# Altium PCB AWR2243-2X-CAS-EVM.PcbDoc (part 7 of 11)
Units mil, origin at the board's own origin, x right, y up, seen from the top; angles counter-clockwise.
Board outline 5118.11 x 3937.01 mil, 8 copper layers (Layer 1 - Top Layer, Layer 2 - GND, Layer 3 - Signal (Sensitive), Layer 4 - GND / Signal, Layer 5 - Signal, Layer 6 - PWR / Signal, Layer 7 - GND, Layer 8 - Bottom Layer), stack 54.8 mil thick; 629 components, 407 nets, 2243 pads, 3950 vias.
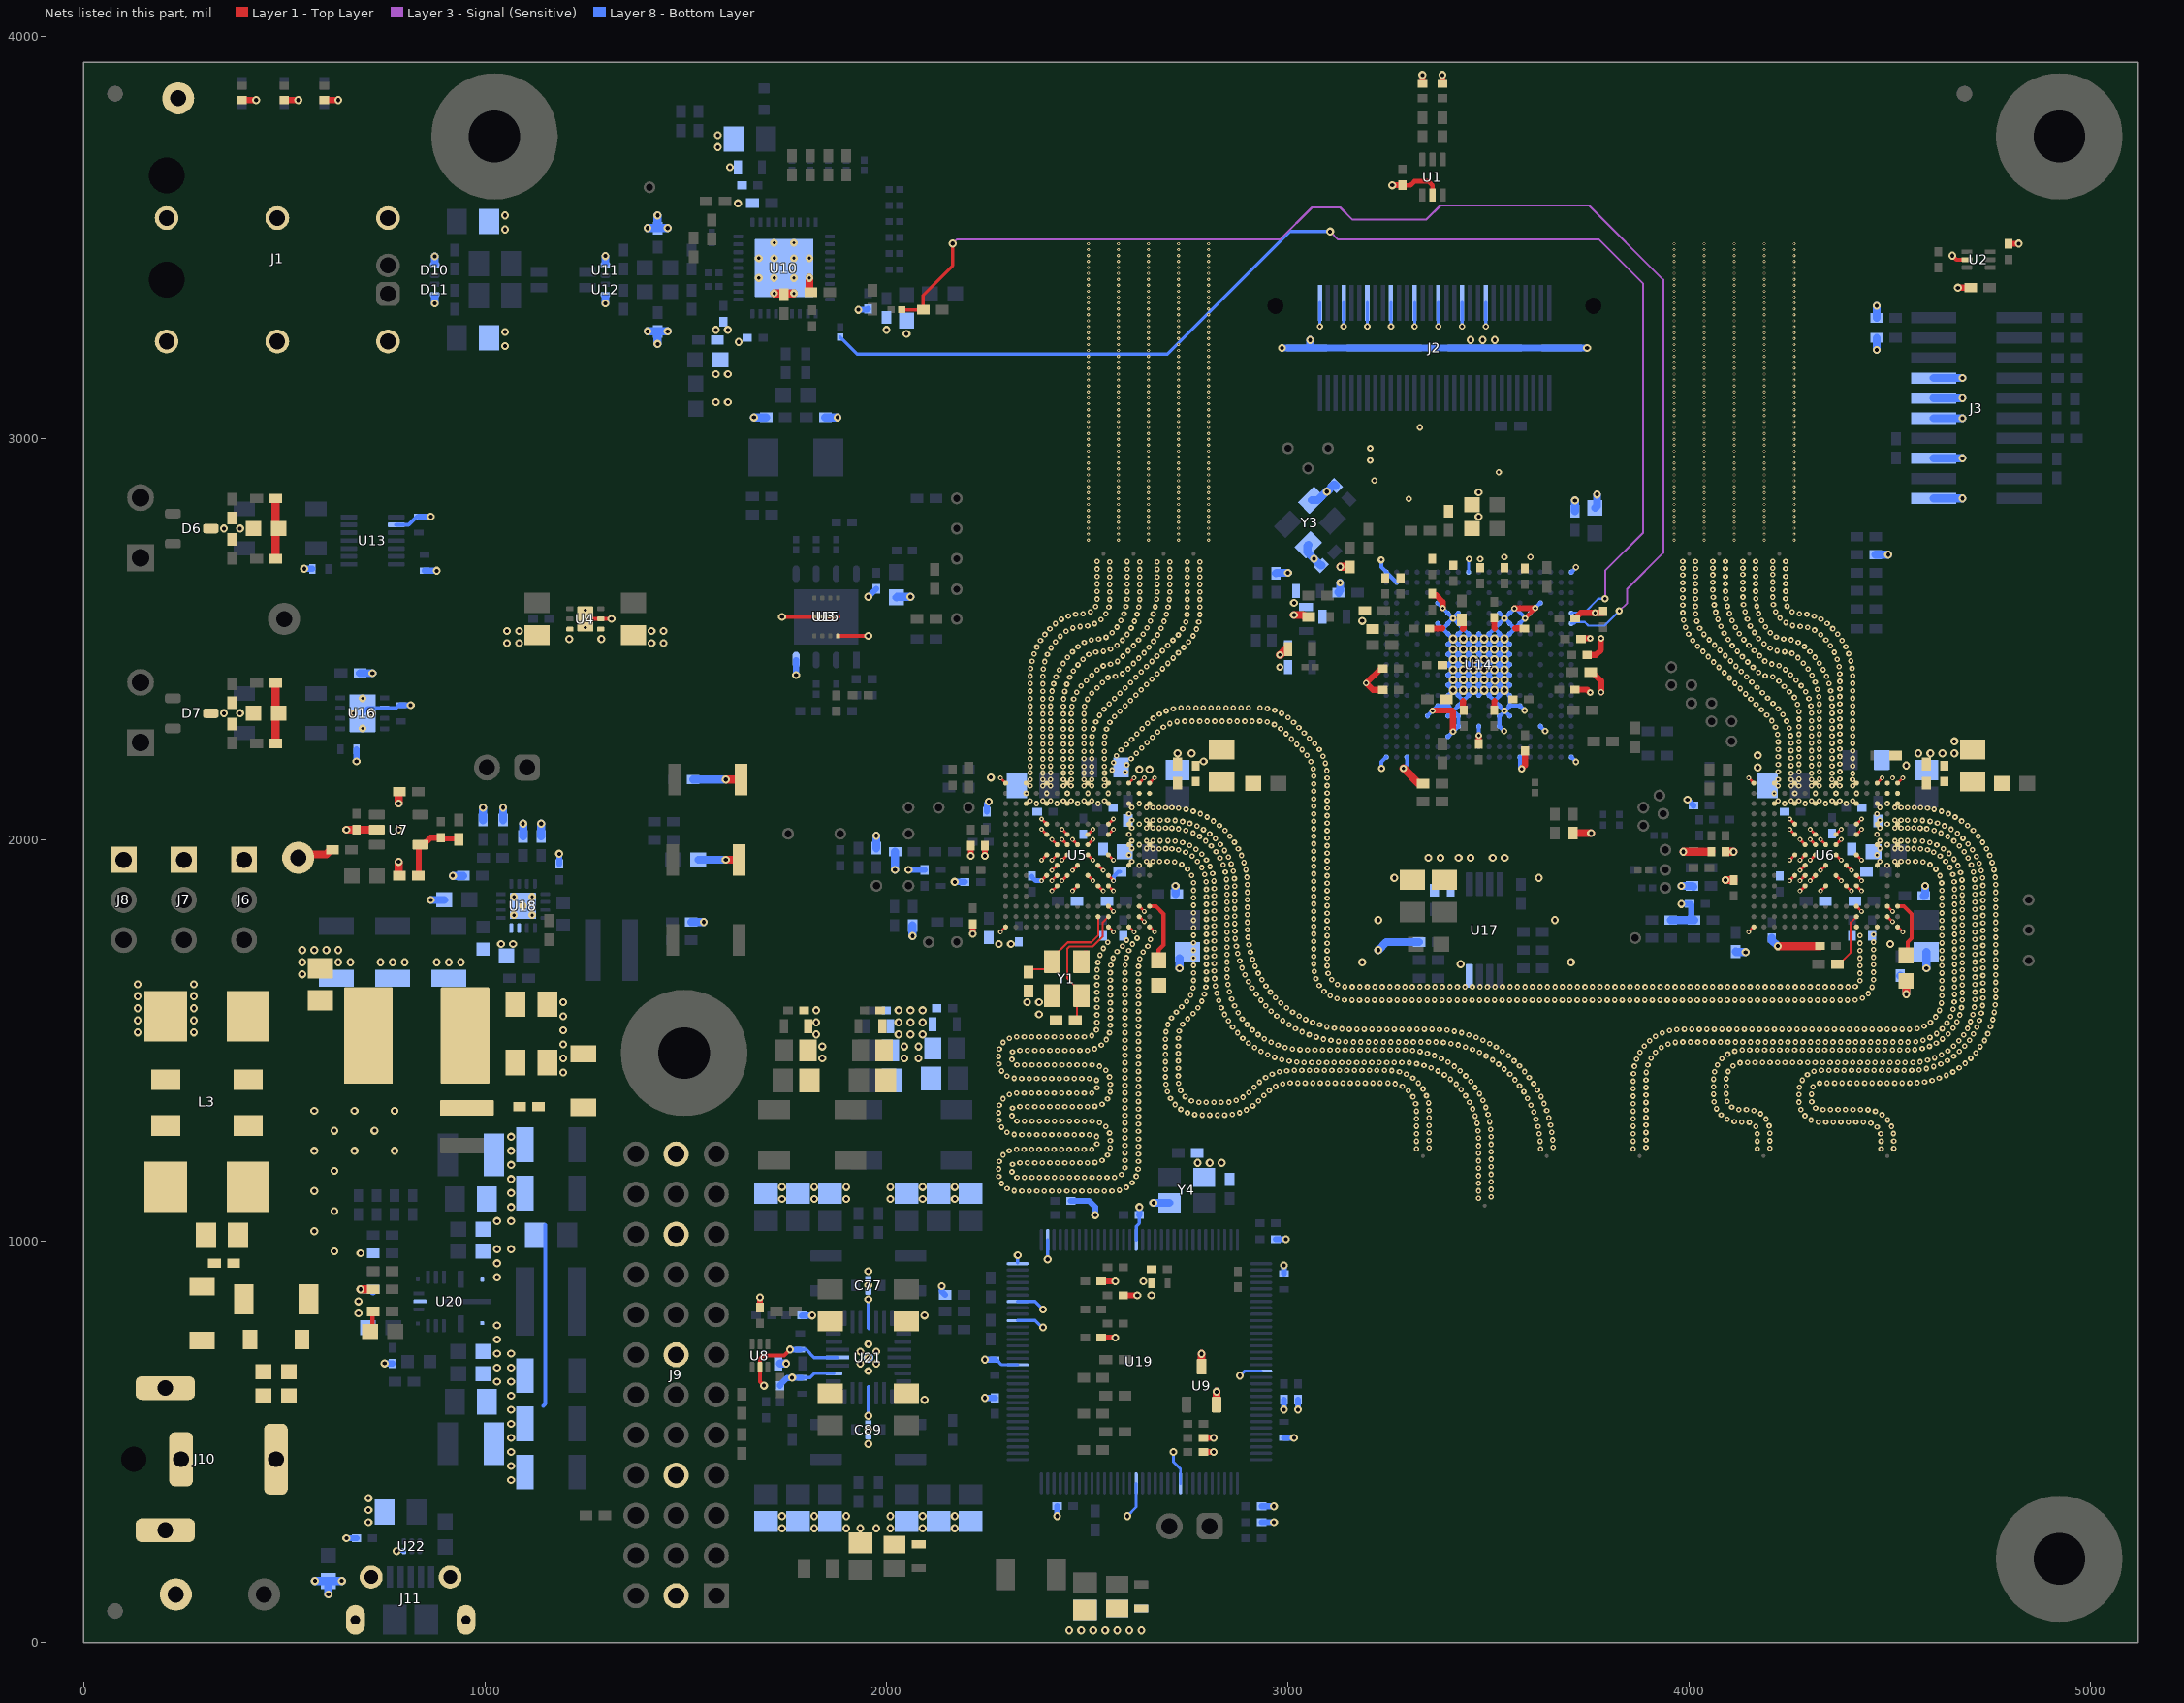
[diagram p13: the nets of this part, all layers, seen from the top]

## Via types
v1: diameter 13.78, hole 5.91, Layer 1 - Top Layer to Layer 2 - GND, tented top, 2104 vias
v2: diameter 20, hole 10, Layer 1 - Top Layer to Layer 8 - Bottom Layer, tented both sides, 831 vias
v3: diameter 7.87, hole 3.94, Layer 1 - Top Layer to Layer 2 - GND, tented top, 510 vias
v4: diameter 12, hole 6, Layer 1 - Top Layer to Layer 8 - Bottom Layer, tented both sides, 176 vias
v5: diameter 16, hole 8, Layer 1 - Top Layer to Layer 8 - Bottom Layer, tented both sides, 138 vias
v6: diameter 13.78, hole 5.91, Layer 1 - Top Layer to Layer 2 - GND, tented both sides, 88 vias
v7: diameter 18, hole 8, Layer 1 - Top Layer to Layer 8 - Bottom Layer, tented both sides, 41 vias
v8: diameter 22, hole 12, Layer 1 - Top Layer to Layer 8 - Bottom Layer, tented both sides, 36 vias
v9: diameter 19.68, hole 7.87, Layer 1 - Top Layer to Layer 8 - Bottom Layer, tented both sides, 26 vias

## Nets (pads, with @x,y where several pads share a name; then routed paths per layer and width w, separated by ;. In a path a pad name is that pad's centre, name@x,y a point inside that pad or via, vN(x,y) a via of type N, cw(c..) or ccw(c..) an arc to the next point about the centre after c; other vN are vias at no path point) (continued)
GND: (continued)
  other v1: 3474.49,1106.77 3506.14,1110.42 2337.18,1125.32 2355.88,1125.32 2374.58,1125.32 2393.28,1125.32 2411.98,1125.32 2430.68,1125.32 2449.38,1125.32 2468.08,1125.32 2486.78,1125.32 2505.48,1125.32 2524.18,1125.32 2542.89,1125.32 2561.59,1125.32 3474.49,1125.47 2318.48,1125.7 2580.21,1127 3506.14,1129.12 2300.56,1131.04 2597.58,1133.93 2286.82,1143.73 3474.49,1144.17 2611.96,1145.89 3506.14,1147.82 2325.03,1158.7 2343.73,1158.7 2362.43,1158.7 2381.14,1158.7 2399.84,1158.7 2418.54,1158.7 2437.24,1158.7 2455.94,1158.7 2474.64,1158.7 2493.34,1158.7 2512.04,1158.7 2530.74,1158.7 2549.44,1158.7 2568.14,1158.76 2280.12,1161.18 2622,1161.67 3474.49,1162.87 2585.37,1166.03 3506.14,1166.52 2312.68,1172.74 2279.29,1179.87 2626.9,1179.71 3474.49,1181.57 2593.94,1182.65 3506.14,1185.22 2314.02,1191.39 2332.31,1195.32 2351.01,1195.32 2369.71,1195.32 2388.41,1195.32 2407.11,1195.32 2425.81,1195.32 2444.51,1195.32 2463.21,1195.32 2481.91,1195.32 2500.61,1195.32 2519.31,1195.81 2281.2,1198.47 2627.68,1198.4 3474.49,1200.27 2537.14,1201.44 2594.29,1201.35 3506.14,1203.92 2550.65,1214.37 2290.29,1214.81 2627.68,1217.1 3474.49,1218.97 2594.29,1220.05 3506.14,1222.62 2305.73,1225.37 2324.13,1228.7 2342.83,1228.7 2361.53,1228.7 2380.23,1228.7 2398.93,1228.7 2417.63,1228.7 2436.33,1228.7 2455.03,1228.7 2473.73,1228.7 2492.43,1228.7 2511.14,1228.7 3320.2,1230.2 3628.93,1230.19 3860.16,1230.2 4168.7,1230.2 4477.25,1230.2 4200.35,1231.32 4508.9,1230.74 2556.96,1231.98 3351.85,1232.21 3891.81,1233.36 3660.27,1233.62 2627.68,1235.8 3474.49,1237.68 2594.29,1238.75 3506.14,1241.33 2524.29,1241.99 3320.2,1248.9 3627.91,1248.86 3860.16,1248.9 4168.7,1248.9 4477.25,1248.9 4508.9,1249.44 4200.35,1250.02 2557.68,1250.67 3351.85,1250.91 3659.22,1252.29 3891.81,1252.06 2627.68,1254.5 3474.49,1256.38 2594.29,1257.45 3506.13,1260.03 2523.42,1260.67 2337,1265.32 2355.7,1265.32 2374.4,1265.32 2393.11,1265.32 2411.81,1265.32 2430.51,1265.32 2449.21,1265.32 2467.91,1265.32 2486.61,1265.32 2505.31,1265.32 2318.31,1265.72 3625.92,1267.45 3320.2,1267.6 3860.16,1267.6 4168.7,1267.6 4476.28,1267.57 4507.93,1268.12 2555.59,1269.25 4200.35,1268.72 3351.85,1269.61 2300.41,1271.14 3657.25,1270.89 3891.81,1270.76 2627.68,1273.2 3473.61,1275.06 2594.29,1276.15 3504.9,1278.69 2286.71,1283.87 4467.47,1284.07 2546.17,1285.41 3320.2,1286.3 3622.79,1285.89 3860.16,1286.3 4164.88,1285.9 4502.93,1286.14 4198.4,1287.32 3351.85,1288.31 3654.11,1289.32 3891.81,1289.46 2627.68,1291.9 3470.91,1293.56 4451.76,1294.22 2594.29,1294.85 2530.54,1295.66 4130.33,1296.18 4149.03,1295.82 4339.66,1296.18 4358.36,1296.18 4377.06,1296.18 4395.76,1296.18 4414.46,1296.18 4433.17,1296.18 3502.26,1297.2 4320.97,1296.73 4111.68,1297.58 2325.08,1298.7 2343.78,1298.7 2362.48,1298.7 2381.18,1298.7 2399.88,1298.7 2418.58,1298.7 2437.28,1298.7 2455.98,1298.7 2474.68,1298.7 2493.38,1298.7 2512.08,1298.7 2280.09,1301.36 4302.94,1301.7 4493.26,1302.14 3617.92,1303.95 4094,1303.65 4190.46,1304.25 3320.2,1305 3860.16,1305 3351.85,1307.01 3649.64,1307.48 3891.81,1308.16 2627.68,1310.6 3466.54,1311.75 2312.68,1312.7 4287.69,1312.53 2594.29,1313.55 2786.54,1314.17 2805.24,1314.17 2823.94,1314.17 2842.64,1314.17 2767.87,1315.31 4078.96,1314.77 4479.63,1314.94 2861.28,1315.65 3498.49,1315.52 4177.3,1317.53 2279.29,1320.04 2749.74,1319.9 2879.46,1320.03 3612.25,1321.77 3320.2,1323.7 3860.16,1323.7 4463.05,1323.59 3644.46,1325.45 3351.85,1325.71 4160.48,1325.72 2896.74,1327.18 3891.81,1326.86 4444.75,1327.46 2733.12,1328.46 4123.2,1327.79 4141.9,1327.83 4277.44,1328.17 4332.55,1327.83 4351.25,1327.83 4369.95,1327.83 4388.65,1327.83 4407.35,1327.83 4426.05,1327.83 2627.68,1329.3 3460.53,1329.45 4067.75,1329.74 2314,1331.35 4314.19,1331.42 2594.29,1332.25 3492.48,1333.22 4105.48,1333.75 2332.28,1335.32 2350.98,1335.32 2369.68,1335.32 2388.38,1335.32 2407.08,1335.32 2425.78,1335.32 2444.48,1335.32 2463.18,1335.32 2481.88,1335.32 2500.58,1335.32 2519.28,1335.81 2912.6,1337.09 2281.23,1338.64 3605.09,1339.04 2718.76,1340.45 2537.11,1341.43 3318.2,1342.29 3860.16,1342.4 3637.57,1342.83 3350.2,1344.34 2777.91,1345.93 2796.61,1345.83 2815.31,1345.83 2834.02,1345.83 2852.71,1346.47 3452.28,1346.24 3891.81,1345.56 4272.92,1346.32 4061.59,1347.4 4304.5,1347.41 2627.68,1348 2926.73,1349.35 4094.01,1348.53 2759.61,1349.78 2870.97,1350.51 3485.27,1350.48 2594.29,1350.95 2550.63,1354.35 2290.39,1354.95 2707.51,1355.39 3596.7,1355.76 2887.91,1358.42 2743.95,1359.99 3311.2,1359.64 3630.28,1360.05 3860.16,1361.1 3345,1362.31 3442.55,1362.2 2939.95,1362.57 3891.81,1364.26 2305.88,1365.43 4272.6,1365.01 4060.16,1366.04 4304.25,1366.11 2627.68,1366.7 3476.88,1367.2 4091.81,1367.1 2324.29,1368.7 2342.99,1368.7 2361.69,1368.7 2380.39,1368.7 2399.09,1368.7 2417.8,1368.7 2436.5,1368.7 2455.2,1368.7 2473.9,1368.7 2492.6,1368.7 2511.3,1368.7 2594.29,1369.65 2902.69,1369.87 2556.95,1371.95 2699.77,1372.41 3587.58,1372.08 2732.73,1374.95 2953.64,1375.31 3299.97,1374.59 3621.23,1376.42 3431.41,1377.23 3336.54,1378.98 3860.16,1379.8 2524.29,1382.15 2915.82,1383.2 3466.61,1382.82 3891.81,1382.96 4273.93,1383.67 4307.93,1384.45 2627.68,1385.41 2969.43,1385.33 3284.78,1385.49 4060.16,1384.74 4091.81,1385.8 3576.76,1387.33 2594.29,1388.36 2557.68,1390.64 2695.91,1390.71 3418.96,1391.18 2987.02,1391.67 3267.33,1392.23 3611.67,1392.49 2727.31,1392.85 3005.59,1393.92 3024.29,1393.82 3042.99,1393.82 3061.69,1393.82 3080.39,1393.82 3099.09,1393.82 3117.79,1393.82 3136.49,1393.82 3155.19,1393.82 3173.89,1393.82 3192.6,1393.82 3211.3,1393.82 3230,1393.82 3248.7,1393.82 3325.1,1393.77 4324.18,1393.7 4342.88,1393.82 4361.59,1393.82 4380.29,1393.82 4398.99,1393.82 4417.69,1393.82 4436.39,1393.82 4455.09,1393.82 4473.79,1393.82 4492.49,1393.82 4511.19,1393.82 4529.89,1393.82 4548.59,1393.82 4567.27,1394.73 2929.41,1396.04 4585.86,1396.83 3455.29,1397.71 3860.16,1398.5 4604.2,1400.48 2523.32,1400.82 4280.98,1400.99 3565.19,1402.03 3891.81,1401.66 4060.2,1403.44 2627.68,1404.11 3404.9,1403.51 4091.77,1404.5 2336.86,1405.32 2355.56,1405.32 2374.26,1405.32 2392.96,1405.32 2411.66,1405.32 2430.36,1405.32 2449.07,1405.32 2467.77,1405.32 2486.47,1405.32 2505.17,1405.32 2318.16,1405.74 3311.08,1406.16 4621.99,1406.22 2594.29,1407.06 2944.36,1407.27 3600.85,1407.74 2555.61,1409.22 2695.16,1409.39 2300.28,1411.22 2726.81,1411.55 3442.96,1411.77 4639.35,1413.17 3389.7,1414.4 4293.81,1414.59 2960.93,1415.94 3295,1415.7 3552.73,1415.97 3860.61,1417.2 3892.44,1420.36 4656.13,1421.45 2978.68,1421.83 3277.41,1422.04 3589.2,1422.37 4062.89,1421.95 2627.68,1422.81 4096.54,1422.58 4310.4,1423.23 2286.62,1423.98 3373.57,1423.86 3429.01,1424.22 2546.2,1425.38 2997.15,1424.78 3015.84,1425.47 3034.54,1425.47 3053.24,1425.47 3071.94,1425.47 3090.64,1425.47 3109.34,1425.47 3128.04,1425.47 3146.74,1425.47 3165.44,1425.47 3184.14,1425.47 3202.84,1425.47 3221.54,1425.47 3240.24,1425.47 3258.94,1424.98 4328.96,1425.47 4347.66,1425.47 4366.37,1425.47 4385.07,1425.47 4403.77,1425.47 4422.47,1425.47 4441.17,1425.47 4459.87,1425.47 4478.57,1425.47 4497.27,1425.47 4515.97,1425.47 4534.67,1425.47 4553.37,1425.35 2594.29,1425.76 4572.03,1426.57 2695.16,1428.09 3539.01,1428.68 2726.81,1430.25 4590.45,1429.82 3356.65,1431.82 4671.76,1431.7 4608.46,1434.85 2530.57,1435.65 3414.31,1435.78 3576.74,1436.32 3863.06,1435.74 4108.81,1436.69 3338.94,1437.84 2325.11,1438.7 2343.81,1438.7 2362.51,1438.7 2381.21,1438.7 2399.91,1438.7 2418.61,1438.7 2437.31,1438.7 2456.01,1438.7 2474.71,1438.7 2493.42,1438.7 2512.12,1438.7 3896.43,1438.63 4069.97,1439.26 2280.07,1441.5 3524.74,1440.76 2627.68,1441.51 3320.68,1441.89 4625.9,1441.61 4686.65,1443.02 2594.29,1444.46 3302.14,1444.28 4125.94,1444.2 3040.34,1444.91 3059.04,1445 3077.74,1445 3096.44,1445 3115.14,1445 3133.84,1445 3152.54,1445 3171.24,1445 3189.94,1445 3208.65,1445 3227.35,1445 3246.05,1445 3264.75,1445 3283.45,1445 4144.62,1445 4163.32,1445 4182.02,1445 4200.73,1445 4219.43,1445 4238.13,1445 4256.83,1445 4275.53,1445 4294.23,1445 4312.93,1445 4331.63,1445 4350.33,1445 4369.03,1445 4387.73,1445 4406.43,1445 4425.14,1445 4443.84,1445 4462.54,1445 4481.24,1445 4499.94,1445 4518.64,1445 4537.34,1445 4556.04,1445.19 3021.67,1446.1 3398.76,1446.17 2695.16,1446.79 4574.68,1446.66 3003.12,1448.39 2726.81,1448.95 3563.22,1449.24 4642.59,1450.05 4592.94,1450.71 2984.77,1452.04 3509.48,1451.58 2312.68,1452.67 3868.46,1453.64 4081.01,1454.35 3382.13,1454.71 4700.65,1455.42 3904.28,1455.6 4610.68,1456.64 2966.97,1457.75 2279.29,1460.19 2627.68,1460.21 4658.14,1460.44 3493.5,1461.28 3364.99,1462.21 3549.27,1461.7 2594.29,1463.16 2949.51,1464.46 4627.7,1464.37 2695.16,1465.5 4095.74,1465.87 2726.81,1467.65 3347.29,1468.22 4713.07,1469.4 3477.09,1470.26 3876.65,1470.45 3915.62,1470.47 2313.98,1471.32 3329.04,1472.31 4672.48,1472.43 2932.74,1472.73 3534.13,1472.67 4112.89,1473.32 4643.65,1474.14 2332.25,1475.32 2350.95,1475.32 2369.65,1475.32 2388.35,1475.32 2407.05,1475.32 2425.76,1475.32 2444.46,1475.32 2463.16,1475.32 2481.86,1475.32 2500.56,1475.47 3310.57,1475.26 3291.91,1476.48 4131.33,1476.44 3030.1,1477.07 3048.8,1476.65 3067.5,1476.65 3086.2,1476.65 3104.9,1476.65 3123.6,1476.65 3142.3,1476.65 3161,1476.65 3179.7,1476.65 3198.41,1476.65 3217.11,1476.65 3235.81,1476.65 3254.51,1476.65 3273.21,1476.65 3459.81,1477.42 4150.03,1476.65 4168.73,1476.65 4187.44,1476.65 4206.14,1476.65 4224.84,1476.65 4243.54,1476.65 4262.24,1476.65 4280.94,1476.65 4299.64,1476.65 4318.34,1476.65 4337.04,1476.65 4355.74,1476.65 4374.44,1476.65 4393.14,1476.65 4411.84,1476.65 4430.55,1476.65 4449.25,1476.65 4467.95,1476.65 4486.65,1476.65 4505.35,1476.65 4524.05,1476.65 4542.75,1476.65 4561.44,1477.18 2281.26,1478.78 2518.87,1479.27 2627.68,1478.91 3011.48,1478.8 4579.94,1479.95 2594.29,1481.86 2993.14,1482.45 3930,1482.43 2916.84,1482.58 3518.73,1483.28 2695.16,1484.2 3442.21,1483.72 4724.43,1484.25 4597.84,1485.37 2726.81,1486.35 3887.44,1485.73 4658.11,1486.01 4685.59,1485.77 2535.15,1488.46 2975.33,1488.13 3424.24,1488.9 3946.74,1490.77 3405.86,1492.37 3502.36,1492.33 2901.53,1493.32 4614.76,1493.33 2290.48,1495.06 2958.06,1495.32 3387.35,1495.01 3964.88,1495.28 3162.97,1496.18 3181.67,1496.18 3200.37,1496.18 3219.07,1496.18 3237.77,1496.18 3256.47,1496.18 3275.17,1496.18 3293.87,1496.18 3312.57,1496.18 3331.28,1496.18 3349.98,1496.18 3368.68,1496.06 3983.56,1496.18 4002.26,1496.18 4020.97,1496.18 4039.67,1496.18 4058.37,1496.18 4077.07,1496.18 4095.77,1496.18 4114.47,1496.18 4133.17,1496.18 4151.87,1496.18 4170.57,1496.18 4189.27,1496.18 4207.97,1496.18 4226.67,1496.18 4245.37,1496.18 4264.08,1496.18 4282.78,1496.18 4301.48,1496.18 4320.18,1496.18 4338.88,1496.18 4357.58,1496.18 4376.28,1496.18 4394.98,1496.18 4413.68,1496.18 4432.38,1496.18 4451.08,1496.18 4469.78,1496.18 4488.49,1496.18 4507.19,1496.18 4525.89,1496.18 4544.59,1496.18 3144.27,1496.54 4563.26,1497.14 2627.68,1497.61 3125.6,1497.59 3900.54,1499.08 4671.25,1499.3 3107.08,1500.16 4697.33,1500.32 4734.74,1499.86 2594.29,1500.56 3485.67,1500.76 4581.62,1500.73 2547.86,1502.18 2695.16,1502.9 3088.66,1503.38 2941.47,1503.96 4630.34,1503.67 2306,1505.48 2726.81,1505.05 2887.47,1505.65 4599.1,1507.37 3468.39,1507.91 2324.42,1508.7 2343.12,1508.7 2361.82,1508.7 2380.53,1508.7 2399.23,1508.7 2417.93,1508.7 2436.63,1508.7 2455.33,1508.7 2474.03,1508.7 2492.73,1508.7 3070.67,1508.52 3915.6,1510.15 2511.16,1511.86 2925.92,1514.35 3052.9,1514.32 3450.71,1514.01 4682.95,1513.89 2627.68,1516.31 4644.27,1516.15 4707.6,1515.96 4615.21,1516.87 4743.01,1516.63 2555.52,1519.24 2594.29,1519.26 2874.43,1519.05 3432.74,1519.18 3932.25,1518.67 3035.62,1521.48 2696.36,1521.56 3414.4,1522.83 2729.12,1523.61 3950.05,1524.4 2523,1526.34 2911.58,1526.35 3395.96,1525.96 3377.3,1527.09 3968.54,1527.21 3152.9,1527.83 3171.6,1527.83 3190.3,1527.83 3209,1527.83 3227.7,1527.83 3246.41,1527.83 3265.11,1527.83 3283.81,1527.83 3302.51,1527.83 3321.21,1527.83 3339.91,1527.83 3358.61,1527.83 3987.23,1527.83 4005.93,1527.83 4024.64,1527.83 4043.34,1527.83 4062.04,1527.83 4080.74,1527.83 4099.44,1527.83 4118.14,1527.83 4136.84,1527.83 4155.54,1527.83 4174.24,1527.83 4192.94,1527.83 4211.64,1527.83 4230.34,1527.83 4249.04,1527.83 4267.75,1527.83 4286.45,1527.83 4305.15,1527.83 4323.85,1527.83 4342.55,1527.83 4361.25,1527.83 4379.95,1527.83 4398.65,1527.83 4417.35,1527.83 4436.05,1527.83 4454.75,1527.83 4473.45,1527.83 4492.16,1527.83 4510.86,1527.83 4529.56,1527.83 4548.26,1527.83 3134.22,1528.61 4566.91,1529.14 4629.48,1528.95 3018.87,1529.79 4692.72,1529.84 3115.62,1530.62 4656.24,1530.52 2862.17,1533.17 4715.87,1532.73 3097.19,1533.75 4750.02,1533.97 2627.68,1535.01 4584.58,1535.28 2557.68,1537.82 2594.29,1537.96 3002.5,1538.83 3079.18,1538.8 2701.12,1539.65 2737.53,1540.31 2898.31,1539.53 4641.34,1543.41 2524.29,1544.99 3061.48,1544.82 4600.33,1545.36 4666.01,1546.46 4700.26,1546.95 2851.77,1548.72 2987.12,1549.48 4722.33,1550.28 3044.2,1551.97 4755.81,1551.75 2627.68,1553.71 2750.32,1553.96 2886.22,1553.79 2709.89,1556.16 2557.68,1556.52 2594.29,1556.66 4613.3,1558.83 4650.35,1559.8 2972.1,1560.62 3027.73,1560.83 2524.29,1563.69 4673.16,1563.74 2842.36,1564.88 4705.98,1564.76 2763.57,1567.15 4727.05,1568.37 2875.83,1569.34 2722,1570.41 4759.46,1570.09 3011.76,1570.57 2627.68,1572.41 2958.16,1573.08 2557.68,1575.22 2594.29,1575.36 4622.78,1574.95 4656.47,1577.47 2775.59,1581.48 2996.51,1581.39 2524.29,1582.4 2834.09,1581.65 4677.74,1581.87 4709.83,1583.06 2735.23,1583.63 2867.08,1585.87 2944.91,1586.28 4729.97,1586.84 4761.62,1588.67 2627.68,1591.11 4627.62,1593.01 2557.68,1593.92 2594.29,1594.06 2982.37,1593.63 4659.51,1595.92 2747.92,1597.36 2785.06,1597.6 2827.85,1599.28 2932.45,1600.22 3159.45,1600.32 3178.15,1600.32 3196.85,1600.32 3215.55,1600.32 3234.25,1600.32 3252.95,1600.32 3271.66,1600.32 3290.36,1600.32 3309.06,1600.32 3327.76,1600.32 3346.46,1600.32 3365.16,1600.32 3383.86,1600.32 3402.56,1600.32 3421.26,1600.32 3439.96,1600.32 3458.66,1600.32 3477.36,1600.32 3496.07,1600.32 3514.77,1600.32 3533.47,1600.32 3552.17,1600.32 3570.87,1600.32 3589.57,1600.32 3608.27,1600.32 3626.97,1600.32 3645.67,1600.32 3664.37,1600.32 3683.07,1600.32 3701.77,1600.32 3720.47,1600.32 3739.18,1600.32 3757.88,1600.32 3776.58,1600.32 3795.28,1600.32 3813.98,1600.32 3832.68,1600.32 3851.38,1600.32 3870.08,1600.32 3888.78,1600.32 3907.48,1600.32 3926.18,1600.32 3944.88,1600.32 3963.59,1600.32 3982.29,1600.32 4000.99,1600.32 4019.69,1600.32 4038.39,1600.32 4057.09,1600.32 4075.79,1600.32 4094.49,1600.32 4113.19,1600.32 4131.89,1600.32 4150.59,1600.32 4169.29,1600.32 4187.99,1600.32 4206.7,1600.32 4225.4,1600.32 4244.1,1600.32 4262.8,1600.32 4281.5,1600.32 4300.2,1600.32 4318.9,1600.32 4337.6,1600.32 4356.3,1600.32 4375,1600.32 4393.7,1600.32 4679.64,1600.48 2524.29,1601.1 3140.76,1600.85 4412.4,1600.78 4711.29,1601.7 2859.78,1603.08 3122.37,1604.24 4430.46,1605.64 4730.91,1605.52 2968.92,1606.62 4762.56,1607.34 2627.68,1609.82 3105.2,1611.65 4628.55,1611.69 2557.68,1612.62 2594.29,1612.77 2757.76,1613.27 2791.81,1615.04 2921.24,1615.19 4660.2,1614.61 2822.62,1617.23 4445.44,1616.83 4679.73,1619.18 2524.29,1619.8 4711.38,1620.4 2853.97,1620.86 2956.46,1620.56 3090.12,1622.71 4730.91,1624.22 4762.56,1626.04 2627.68,1628.52 4628.55,1630.39 2557.68,1631.32 2594.29,1631.47 2763.77,1630.98 2910.53,1630.52 2795.66,1633.34 4455.01,1632.9 4660.2,1633.31 3141.52,1633.99 3160.21,1633.7 3178.91,1633.7 3197.62,1633.7 3216.32,1633.7 3235.02,1633.7 3253.72,1633.7 3272.42,1633.7 3291.12,1633.7 3309.82,1633.7 3328.52,1633.7 3347.22,1633.7 3365.92,1633.7 3384.62,1633.7 3403.32,1633.7 3422.02,1633.7 3440.73,1633.7 3459.43,1633.7 3478.13,1633.7 3496.83,1633.7 3515.53,1633.7 3534.23,1633.7 3552.93,1633.7 3571.63,1633.7 3590.33,1633.7 3609.03,1633.7 3627.73,1633.7 3646.43,1633.7 3665.14,1633.7 3683.84,1633.7 3702.54,1633.7 3721.24,1633.7 3739.94,1633.7 3758.64,1633.7 3777.34,1633.7 3796.04,1633.7 3814.74,1633.7 3833.44,1633.7 3852.14,1633.7 3870.84,1633.7 3889.54,1633.7 3908.25,1633.7 3926.95,1633.7 3945.65,1633.7 3964.35,1633.7 3983.05,1633.7 4001.75,1633.7 4020.45,1633.7 4039.15,1633.7 4057.85,1633.7 4076.55,1633.7 4095.25,1633.7 4113.95,1633.7 4132.66,1633.7 4151.36,1633.7 4170.06,1633.7 4188.76,1633.7 4207.46,1633.7 4226.16,1633.7 4244.86,1633.7 4263.56,1633.7 4282.26,1633.7 4300.96,1633.7 4319.66,1633.7 4338.36,1633.7 4357.06,1633.7 4375.77,1633.7 4394.47,1633.7 4413.16,1634.26 2818.97,1635.57 2945.33,1635.6 3078.06,1637 2524.29,1638.5 4679.73,1637.88 2850.33,1639.2 3123.58,1639.3 4711.38,1639.1 4730.91,1642.92 4762.56,1644.74 2627.68,1647.22 2901.48,1646.89 4424.94,1648.78 4628.55,1649.09 2557.68,1650.02 2594.29,1650.17 2765.16,1649.62 2935.04,1651.21 3109.02,1651.04 4458.42,1651.28 2796.81,1652.01 4660.2,1652.01 2817.18,1654.19 3069.64,1653.7 2524.29,1657.2 4679.73,1656.58 2848.47,1657.81 4711.38,1657.81 4730.91,1661.62 4762.56,1663.44 2893.1,1663.6 2627.68,1665.92 3100.02,1667.43 4425.04,1667.48 2765.16,1668.33 2925.99,1667.58 4628.55,1667.79 2557.68,1668.73 2594.29,1668.87 4458.42,1669.98 2796.81,1670.71 4660.2,1670.71 3065.31,1671.89 2816.34,1672.87 4679.73,1675.28 2524.54,1675.9 2847.99,1676.51 4711.38,1676.51 4730.91,1680.33 2885.94,1680.88 4762.56,1682.15 2627.72,1684.62 2918.42,1684.68 3097.68,1685.98 4425.04,1686.18 4628.55,1686.5 2558.89,1687.39 2765.16,1687.03 2594.79,1687.56 2796.81,1689.41 4458.42,1688.68 4660.2,1689.41 3064.29,1690.56 2816.34,1691.57 2526.59,1694.49 4679.73,1693.98 2847.99,1695.21 4711.38,1695.21 2880.06,1698.63 4730.91,1699.03 4762.56,1700.85 2911.78,1702.16 2631.15,1703 2564.79,1705.13 3097.68,1704.68 4425.04,1704.88 4628.55,1705.2 2597.54,1706.06 2765.16,1705.73 4458.42,1707.38 2796.81,1708.11 4660.2,1708.11 3064.29,1709.26 2816.34,1710.27 2531.89,1712.42 4679.73,1712.68 2847.99,1713.91 4711.38,1713.91 2874.88,1716.6 4730.91,1717.73 2639.06,1719.95 2906.6,1720.13 4762.56,1719.55 2574.59,1721.06 3097.68,1723.38 2603.6,1723.75 2765.16,1724.43 4425.04,1723.58 4628.55,1723.9 4458.42,1726.09 2796.81,1726.81 4660.2,1726.81 3064.29,1727.97 2540.16,1729.19 2816.34,1728.97 4679.73,1731.38 2847.99,1732.61 4711.38,1732.61 2650.89,1734.43 2587.33,1734.75 2871.62,1735.02 4730.91,1736.43 2902.95,1738.47 4762.56,1738.25 2612.78,1740.04 3097.68,1742.08 4425.04,1742.28 2765.16,1743.13 4628.55,1742.6 2551,1744.43 4458.42,1744.79 2796.81,1745.51 4660.2,1745.51 3064.29,1746.67 2816.34,1747.67 2598.46,1749.78 4679.73,1750.08 2847.99,1751.31 4711.38,1751.31 2657.48,1751.93 2868.97,1753.53 2624.29,1754.78 4730.91,1755.13 2900.28,1756.98 4762.56,1756.95 3097.68,1760.78 4425.04,1760.98 4628.55,1761.3 2765.16,1761.83 4458.42,1763.49 2796.81,1764.21 4660.2,1764.21 3064.29,1765.37 2816.34,1766.37 4679.73,1768.78 2847.99,1770.01 4711.38,1770.01 2867.92,1772.2 4730.91,1773.83 2899.23,1775.65 4762.56,1775.65 3097.68,1779.48 4628.55,1780 2765.16,1780.53 2796.81,1782.92 4660.2,1782.92 3064.29,1784.07 2816.34,1785.08 4679.73,1787.48 2847.99,1788.71 4711.38,1788.71 2867.52,1790.9 4730.91,1792.53 2899.17,1794.35 4762.56,1794.35 3097.68,1798.19 2765.16,1799.23 4628.55,1798.7 2796.81,1801.62 4660.2,1801.62 3064.29,1802.77 2816.34,1803.78 4679.73,1806.19 2847.99,1807.41 4711.38,1807.41 2867.52,1809.6 4730.91,1811.23 2899.17,1813.05 4762.56,1813.05 3097.68,1816.89 4628.55,1817.4 2765.16,1817.93 2796.81,1820.32 4660.2,1820.32 3064.29,1821.47 2816.34,1822.48 4679.73,1824.89 2847.99,1826.11 4711.38,1826.11 2867.52,1828.3 4730.91,1829.93 2899.17,1831.75 4762.56,1831.75 3097.68,1835.59 4628.55,1836.1 2765.16,1836.63 2796.81,1839.02 4660.2,1839.02 3064.29,1840.17 2816.34,1841.18 4679.73,1843.59 2847.99,1844.81 4711.38,1844.81 2867.52,1847 4730.91,1848.63 2899.17,1850.45 4762.56,1850.45 3097.68,1854.29 2765.16,1855.33 4628.55,1854.8 2796.81,1857.72 4660.2,1857.72 3064.29,1858.87 2816.34,1859.88 4679.73,1862.29 2847.99,1863.51 4711.38,1863.51 2867.52,1865.7 4730.91,1867.33 2899.17,1869.15 4762.56,1869.15 3097.68,1872.99 4628.55,1873.5 2765.16,1874.03 2796.81,1876.42 4660.2,1876.42 3064.29,1877.57 2816.34,1878.58 4679.73,1880.99 2847.99,1882.21 4711.38,1882.21 2867.52,1884.4 4730.91,1886.03 2899.18,1887.85 4762.57,1887.85 3097.68,1891.69 4628.17,1892.2 2764.73,1892.73 2796.1,1895.11 4659.49,1895.11 3064.29,1896.27 2815.72,1897.27 4678.92,1899.67 2846.99,1900.89 4710.38,1900.89 2866.66,1903.08 4729.94,1904.71 2897.96,1906.51 4761.35,1906.51 3097.68,1910.39 4623.8,1910.38 2760.16,1910.86 2792.51,1913.46 4655.9,1913.46 3064.29,1914.97 2812.43,1915.68 4675.26,1918.01 2843.91,1919.33 4707.3,1919.33 2863.66,1921.54 4726.73,1923.13 2895.05,1924.99 4758.44,1924.99 4613.65,1926.09 2749.92,1926.51 3097.68,1929.09 2785.23,1930.69 4648.62,1930.69 2806.1,1933.28 3064.29,1933.67 4668.58,1935.48 2838.51,1937.24 4701.9,1937.24 2735.35,1938.24 4599.21,1937.98 2858.58,1939.54 4721.45,1941.07 2890.58,1943.15 4753.96,1943.15 2717.93,1945.06 4581.84,1944.9 2663.6,1946.18 2680.57,1946.18 2699.27,1946.18 2774.58,1946.05 4526.98,1946.18 4544.48,1946.18 4563.18,1946.18 4637.96,1946.05 3097.68,1947.79 2796.9,1949.56 3064.29,1952.37 4659.05,1951.57 2830.88,1954.31 4694.27,1954.31 2851.49,1956.84 4714.16,1958.29 2761,1958.91 4624.38,1958.91 2884.45,1960.81 4747.84,1960.81 2785.1,1964.06 3097.68,1966.49 4646.86,1965.75 2745.07,1968.71 4608.45,1968.71 2821.02,1970.2 4684.4,1970.2 3064.29,1971.08 2842.47,1973.22 2727.47,1975.04 4592.98,1975.04 4704.95,1974.57 2771.03,1976.38 2663.6,1977.83 2679.21,1977.66 2695.25,1977.83 2710.95,1977.63 2876.3,1977.65 4526.98,1977.83 4542.98,1977.83 4558.98,1977.83 4575.98,1977.63 4632.41,1977.62 4739.69,1977.65 2808.99,1984.52 3097.68,1985.19 4672.38,1984.52 2754.99,1985.99 4616.17,1986.9 2831.65,1988.48 3064.29,1989.78 4693.96,1989.7 2737.55,1992.76 4598.61,1993.32 2866.65,1993.66 4730.03,1993.66 2719.23,1996.51 2663.6,1997.36 2681.85,1997.36 2700.55,1997.36 2795.18,1997.13 4526.98,1997.36 4542.83,1997.36 4561.53,1997.36 4580.22,1996.7 4658.56,1997.13 2819.17,2002.4 4681.32,2003.48 3097.68,2003.89 2779.87,2007.87 3064.29,2008.48 4643.26,2007.87 2855.67,2008.8 4719.05,2008.8 2805.11,2014.73 4667.19,2015.74 2763.33,2016.59 4626.71,2016.59 2745.81,2023.13 2843.34,2022.86 3097.68,2022.6 4609.2,2023.13 4706.72,2022.86 2789.62,2025.22 4651.64,2026.13 2727.59,2027.35 3064.29,2027.18 4590.98,2027.35 2663.6,2029.01 2679.21,2028.84 2695.25,2029.01 2710.95,2028.87 4526.98,2029.01 4542.98,2029.01 4558.98,2029.01 4574.98,2028.87 2773.05,2033.88 2829.37,2035.3 4634.97,2034.6 4692.76,2035.3 2755.59,2040.59 3097.68,2041.3 4617.44,2041.12 2737.49,2045.29 2814.4,2046.5 3064.29,2045.88 4599.29,2045.6 4677.78,2046.5 2718.97,2047.89 4580.74,2047.99 2663.6,2048.54 2681.58,2048.54 2700.28,2048.54 4526.98,2048.54 4543.35,2048.54 4562.05,2048.54 2798.52,2056.39 4661.91,2056.39 3097.68,2060 2781.75,2064.66 3064.29,2064.58 4645.14,2064.66 2764.13,2070.92 4627.52,2070.92 2746.04,2075.66 4609.43,2075.66 2727.61,2078.85 3097.68,2078.7 4592.98,2078.85 2663.6,2080.2 2679.21,2080.02 2695.25,2080.2 2710.95,2080.07 4526.98,2080.2 4542.98,2080.2 4559.98,2080.2 4575.98,2080.07 3064.29,2083.28 3097.68,2097.4 3064.29,2101.98 3097.68,2116.1 3064.29,2120.68 3097.68,2134.8 3064.29,2139.38 2357.8,2150.25 2389.6,2150.01 2408.98,2150.25 2440.78,2150.01 2460.16,2150.25 2491.96,2150.01 2511.34,2150.25 2543.14,2150.01 4221.18,2150.25 4252.98,2150.01 4303.98,2150.01 4354.98,2150.01 4406.17,2150.01 4272.36,2150.64 4323.54,2150.78 4374.73,2151.05 3097.68,2153.5 3064.29,2158.08 4304.01,2165.43 4355.2,2165.3 4406.38,2165.04 2389.6,2166.26 2440.78,2166.26 2491.96,2166.26 2543.14,2166.26 4252.83,2165.77 2357.8,2166.51 2408.98,2166.51 2460.16,2166.51 2511.34,2166.51 2595.04,2168.36 4221.18,2168.95 4272.36,2169.34 4323.54,2169.48 4374.73,2169.75 3096.71,2172.18 2562.1,2173.5 3063.02,2176.74 2389.45,2182.44 2440.63,2182.43 2357.8,2183.24 2408.98,2183.25 2460.16,2182.83 2491.81,2182.87 2511.34,2182.82 2542.99,2182.88 4252.83,2184.48 4304.01,2184.13 4355.2,2184 4406.38,2183.74 2598.7,2186.7 4221.18,2187.65 4272.36,2188.04 4323.54,2188.18 4374.73,2188.45 3093.37,2190.58 2565.44,2191.9 3057.21,2194.52 2389.45,2201.14 2440.63,2201.13 2357.8,2201.94 2408.98,2201.95 2460.16,2201.53 2491.81,2201.57 2511.34,2201.52 2542.99,2201.58 2609.53,2201.94 4406.38,2202.44 4252.83,2203.18 4304.01,2202.83 4355.2,2202.7 4221.18,2206.36 4272.36,2206.75 4323.54,2206.88 4374.73,2207.15 3087.12,2208.2 2572.98,2209.01 3047.62,2210.57 2622.75,2215.17 2389.45,2219.84 2440.63,2219.83 2460.16,2220.23 2491.81,2220.27 2511.34,2220.22 2542.99,2220.28 2357.8,2220.64 2408.98,2220.65 4355.2,2221.41 4406.38,2221.14 4252.83,2221.88 4304.01,2221.53 2584.28,2223.91 3035.01,2224.38 3078.13,2224.6 4221.18,2225.06 4272.36,2225.45 4323.54,2225.58 4374.73,2225.85 2635.97,2228.39 2597.51,2237.14 3021.78,2237.6 2357.8,2239.35 2389.45,2238.54 2408.98,2239.35 2440.63,2238.53 2460.16,2238.93 2491.81,2238.97 2511.34,2238.92 2542.99,2238.98 3066.63,2239.35 4304.01,2240.23 4355.2,2240.11 4406.38,2239.84 4252.83,2240.58 2649.2,2241.62 4221.18,2243.76 4272.36,2244.15 4323.54,2244.28 4374.73,2244.55 2610.73,2250.36 3008.56,2250.83 3053.72,2252.88 2662.42,2254.84 2389.45,2257.24 2440.63,2257.23 2357.8,2258.05 2408.98,2258.05 2460.16,2257.63 2491.81,2257.67 2512.18,2257.6 2543.81,2257.66 4251.86,2259.25 4304.01,2258.93 4355.2,2258.81 4406.38,2258.54 4219.89,2262.41 4272.36,2262.85 4323.54,2262.98 4374.73,2263.26 2623.95,2263.58 2995.34,2264.05 3040.5,2266.1 2675.64,2268.06 2389.45,2275.94 2440.63,2275.94 2460.16,2276.33 2491.81,2276.37 2515.43,2276.02 2548.18,2275.85 2357.8,2276.75 2408.98,2276.75 2637.18,2276.81 2981.72,2276.86 4406.38,2277.24 4248.36,2277.62 4304.01,2277.63 4355.2,2277.51 3027.27,2279.32 2689.64,2280.47 4214.37,2280.28 4272.36,2281.55 4323.54,2281.68 4374.73,2281.96 2965.95,2286.92 2706.04,2289.46 2650.4,2290.03 2556.41,2292.64 2948.36,2293.27 3014.05,2292.55 2521.6,2293.67 2724.09,2294.32 2357.8,2295.45 2389.45,2294.64 2408.98,2295.45 2440.63,2294.64 2460.16,2295.03 2491.81,2295.07 2742.77,2295.32 2761.47,2295.32 2780.17,2295.32 2798.87,2295.32 2817.57,2295.32 2836.27,2295.32 2854.97,2295.32 2873.67,2295.32 2892.38,2295.32 2911.08,2295.32 2929.78,2295.36 4241.95,2295.19 4204.94,2296.43 4304.01,2296.34 4355.2,2296.21 4406.38,2295.95 4272.36,2300.25 4323.54,2300.39 4374.73,2300.66 2664.33,2302.51 2999.94,2304.82 2568.37,2307.02 2530.54,2310.1 4192.46,2310.36 4232.78,2311.49 2389.45,2313.34 2440.63,2313.34 2679.77,2313.06 2357.8,2314.15 2408.98,2314.15 2460.16,2313.73 2491.81,2313.77 2984.19,2314.91 4304.01,2315.04 4355.2,2314.91 4406.38,2314.65 4272.32,2318.95 4323.54,2319.09 4374.73,2319.36 2581.6,2320.24 2696.7,2321.01 2967.04,2322.35 4179.24,2323.58 2542,2324.87 2714.68,2326.14 4221.11,2326.1 2948.91,2326.95 2733.25,2328.32 2751.95,2328.7 2770.65,2328.7 2789.35,2328.7 2808.05,2328.7 2826.75,2328.7 2845.45,2328.7 2864.15,2328.7 2882.85,2328.7 2901.56,2328.7 2930.28,2328.56 2389.45,2332.04 2440.63,2332.04 2461.57,2332.38 2493.61,2332.38 2357.8,2332.85 2408.98,2332.85 2594.82,2333.46 4406.38,2333.35 4302.48,2333.67 4355.2,2333.61 4166.01,2336.8 4269.05,2337.36 2554.95,2338.36 4323.67,2337.79 4374.73,2338.06 4208.07,2339.51 2608.04,2346.69 2466.23,2350.49 2500.4,2349.81 4152.79,2350.03 2389.45,2350.74 2441.34,2350.73 2357.8,2351.55 2409.87,2351.53 2568.18,2351.58 4297.57,2351.72 4354.25,2352.29 4406.38,2352.05 4194.85,2352.73 4261.32,2354.39 4322.45,2356.45 4374.73,2356.76 2621.27,2359.91 4139.57,2363.25 2511.28,2365.02 2581.4,2364.81 4181.62,2365.95 2474.15,2367.43 2389.45,2369.44 2444.17,2369.21 4249.19,2368.62 4289.43,2368.55 2357.8,2370.25 2412.27,2370.08 4351.75,2370.82 4406.38,2370.75 2634.49,2373.13 4318.89,2374.81 4374.73,2375.46 4126.34,2376.47 2524.55,2378.2 2594.62,2378.03 4168.4,2379.18 4235.97,2381.85 2485.04,2382.63 4278.33,2383.61 2647.71,2386.36 2449.24,2387.21 2389.45,2388.14 2416.39,2388.32 2357.8,2388.95 4347.53,2389.04 4406.38,2389.45 4113.12,2389.7 2537.78,2391.42 2607.85,2391.25 4155.18,2392.4 4313.11,2392.59 4374.73,2394.16 4222.74,2395.07 2497.85,2396.26 4265.43,2397.15 2660.94,2399.58 4099.9,2402.92 2456.47,2404.46 2551.73,2403.86 2621.07,2404.48 2422.4,2406.03 4141.95,2405.62 4207.33,2405.66 2389.45,2406.85 2570.12,2407.28 4341.52,2406.75 2357.75,2407.65 4188.82,2408.33 4406.47,2408.15 2511.08,2409.48 4252.21,2410.37 4305.2,2409.54 2674.16,2412.8 4374.55,2412.86 2587.69,2413.7 4086.67,2416.14 4172.18,2416.86 2634.3,2417.7 4128.73,2418.85 2465.75,2420.7 2430.48,2422.89 2524.32,2422.68 4238.92,2423.52 4333.36,2423.57 4295.29,2425.4 2359.13,2426.3 2390.62,2425.51 2602.04,2425.69 2687.38,2426.03 4405.01,2426.79 4073.45,2429.37 4158.36,2429.46 2647.52,2430.92 4372.58,2431.46 4115.51,2432.07 2539.91,2433.02 4223.1,2433.5 2476.94,2435.68 2558.05,2437.55 4204.88,2437.71 2440.1,2438.93 2615.27,2438.91 2700.61,2439.25 4283.51,2439.92 4323.66,2439.56 4060.23,2442.59 4145.13,2442.68 2394.55,2443.79 2575.6,2444.01 2660.74,2444.15 2362.42,2444.71 4102.28,2445.29 4187.63,2444.95 4401.64,2445.19 2489.7,2449.35 4368.12,2449.62 2628.49,2452.13 2713.83,2452.47 4270.48,2453.34 2451.17,2454 4312.51,2454.57 4047,2455.81 4131.91,2455.9 2588.82,2457.23 2673.97,2457.37 4174.41,2458.17 4089.06,2458.52 2400.93,2461.37 2503.71,2461.73 2367.44,2462.73 4396.55,2463.18 4255.26,2464.2 2641.63,2465.43 2727.05,2465.7 4360.96,2466.89 2463.58,2467.99 2521.44,2467.68 4237,2468.22 2540.06,2469.44 4033.78,2469.04 4119.02,2469.45 4300.05,2468.52 2602.05,2470.45 2687.19,2470.59 4161.19,2471.39 4218.46,2470.69 4075.84,2471.74 2558.02,2474.65 4201,2477.39 2409.64,2477.92 2653.96,2479.49 2740.28,2478.92 2374.59,2480 4389.39,2480.46 2477.15,2480.86 4286.44,2481.34 4020.55,2482.26 4351.43,2482.99 2574.09,2484.21 2615.27,2483.68 2700.41,2483.82 4106.69,2483.51 4062.61,2484.96 4147.96,2484.62 4185.55,2487.93 2492.67,2491.3 4270.84,2491.66 2420.52,2493.13 2752.98,2492.65 2665.14,2494.49 2383.94,2496.2 4008.13,2496.24 2587.73,2497.01 2627.89,2497.48 2713.64,2497.04 4379.97,2496.62 2510.2,2497.81 4049.39,2498.19 4135.41,2498.48 4253.26,2498.03 4339.8,2497.63 4096.08,2498.91 2528.78,2499.94 4234.66,2500.01 4172.64,2501.46 2546.94,2504.39 4216.57,2504.74 2433.22,2506.86 2763.89,2507.83 2675.41,2510.12 2726.8,2510.32 2394.79,2511.44 2599.76,2511.33 4326.77,2511.04 2639.23,2512.35 3997.82,2511.84 4036.34,2511.58 4369.07,2511.81 4124.21,2513.45 2562.06,2515.39 4086.3,2514.85 4161.27,2516.3 4201.61,2515.97 2447.18,2519.3 4311.79,2522.24 2407.1,2525.51 2737.8,2525.44 2772.22,2524.58 4356.72,2525.85 2464.01,2527.45 2609.6,2527.23 2683.79,2526.84 4025.6,2526.89 2649.33,2528.09 3990.17,2528.9 4114.26,2529.28 4294.43,2529.19 2574.18,2529.64 4189.59,2530.3 2482.37,2531 4275.85,2531.34 2501.02,2532.43 4078.03,2531.62 4151.5,2532.25 4257.27,2533.46 2420.74,2538.3 2518.85,2538.08 4343.05,2538.61 4240.01,2540.66 2777.73,2542.45 2745.24,2542.6 2617.75,2544.06 2691.15,2544.03 4018.46,2544.17 2657.6,2544.86 2583.95,2545.58 4105.99,2546.06 4179.82,2546.24 3985.36,2546.98 2534.43,2548.42 2435.98,2549.14 4071.31,2549.08 4144.19,2549.46 4327.76,2549.38 4225.49,2552.44 2452.96,2556.97 4310.73,2557.11 2471.11,2561.51 2748.75,2560.97 2780.29,2560.97 2624.25,2561.59 2664.16,2562.37 2697.16,2561.73 4292.57,2561.56 2489.76,2562.83 2546.54,2562.67 2591.43,2562.72 4015.26,2562.6 4172.45,2563.43 4273.9,2562.75 4099.59,2563.63 3983.52,2565.59 4065.51,2566.85 4138.55,2567.29 2507.83,2567.66 4214.91,2567.86 4255.95,2567.97 2553.99,2579.82 2628.62,2579.78 2669.27,2580.36 2701.27,2579.98 2749.14,2579.67 2780.79,2579.67 2520.73,2581.2 2596.49,2580.73 4015.04,2581.3 4167.5,2581.46 4094.64,2581.66 4243.24,2581.69 3983.39,2584.29 4061.86,2585.2 4134.64,2585.58 4209.1,2585.63 2556.38,2598.37 2630.54,2598.38 2704.42,2598.41 2749.14,2598.37 2780.79,2598.37 2524.73,2599.47 2599.05,2599.25 2672.91,2598.7 4015.04,2600 4091.17,2600.04 4165.06,2600 4239.45,2600 3983.39,2602.99 4059.4,2603.73 4133.17,2604.22 4207.8,2604.29 2556.38,2617.07 2631.18,2617.07 2674.14,2617.37 2705.64,2617.07 2749.14,2617.07 2780.79,2617.07 2524.73,2618.17 2599.53,2617.94 4015.04,2618.7 4089.95,2618.7 4164.64,2618.7 4239.45,2618.7 3983.39,2621.69 4058.18,2622.4 4132.99,2622.92 4207.8,2622.99 2556.38,2635.77 2631.18,2635.77 2674.33,2636.07 2705.98,2635.77 2749.14,2635.77 2780.79,2635.77 2524.73,2636.87 2599.53,2636.65 4015.04,2637.4 4089.84,2637.4 4164.64,2637.4 4239.45,2637.4 3983.39,2640.39 4058.19,2641.1 4132.99,2641.63 4207.8,2641.69 2556.38,2654.47 2631.18,2654.47 2705.98,2654.47 2749.14,2654.47 2780.79,2654.47 2599.53,2655.35 2674.33,2654.77 2524.73,2655.57 4015.04,2656.1 4089.84,2656.1 4164.64,2656.1 4239.45,2656.1 3983.39,2659.09 4058.19,2659.8 4132.99,2660.33 4207.8,2660.39 2556.38,2673.17 2631.18,2673.17 2674.33,2673.47 2705.98,2673.17 2749.14,2673.17 2780.79,2673.17 2524.73,2674.27 2599.53,2674.05 4015.04,2674.8 4089.84,2674.8 4164.64,2674.8 4239.45,2674.8 3983.39,2676.5 4058.19,2676.5 4132.99,2676.5 4207.8,2676.5 2556.38,2691.87 2631.18,2691.87 2674.33,2692.17 2705.98,2691.87 2749.14,2691.87 2780.79,2691.87 2524.73,2692.97 2599.53,2692.75 3983.39,2693.5 4015.04,2693.5 4058.19,2693.5 4089.84,2693.5 4132.99,2693.5 4164.64,2693.5 4207.8,2693.5 4239.45,2693.5
  other v2: 2455,30 2485,30 2515,30 2545,30 2575,30 2605,30 2635,30 1740,285 1820,285 1900,285 1935,285 1975,285 2010,285 2090,285 2170,285 710,300 1740,315 1820,315 1900,315 2010,315 2090,315 2170,315 710,330 710,360 1065,405 1065,440 1065,475 1955,495 1065,510 1955,530 1065,545 1065,580 2095,605 1065,615 1030,650 1065,650 1030,685 1065,685 1935,695 1975,695 1030,720 1065,720 1935,725 1975,725 1030,755 1030,790 2095,815 685,820 685,850 2660,865 1955,890 2640,900 1030,910 1955,925 1030,945 690,970 625,975 1030,980 1065,980 575,1025 1030,1050 1065,1050 625,1075 1065,1085 1740,1105 1820,1105 1900,1105 2010,1105 2090,1105 2170,1105 1065,1120 575,1125 1740,1135 1820,1135 1900,1135 2010,1135 2090,1135 2170,1135 1065,1155 625,1175 1065,1190 2775,1195 2805,1195 2835,1195 575,1225 675,1225 775,1225 1065,1225 1065,1260 625,1275 725,1275 575,1325 675,1325 775,1325 1195,1420 1195,1455 1840,1455 2045,1455 2080,1455 1840,1485 2045,1485 2080,1485 1195,1490 1825,1515 2030,1515 2060,1515 2090,1515 135,1520 275,1520 1195,1525 1825,1545 2030,1545 2060,1545 2090,1545 135,1550 275,1550 1195,1560 2380,1565 1825,1575 2030,1575 2060,1575 2090,1575 135,1580 275,1580 1195,1595 2350,1595 2380,1595 135,1610 275,1610 135,1640 275,1640 545,1665 3430,1690 545,1695 635,1695 665,1695 740,1695 770,1695 800,1695 880,1695 910,1695 940,1695 3185,1695 3705,1695 545,1725 575,1725 605,1725 635,1725 1040,1740 1070,1740 2280,1740 2310,1740 4500,1740 3225,1800 3665,1800 3265,1905 3625,1905 3350,1955 3380,1955 3425,1955 3455,1955 3510,1955 3540,1955 785,2025 2260,2155 2630,2175 2655,2175 4170,2180 4540,2185 2790,2195 4170,2210 2725,2215 2760,2215 4570,2215 4600,2215 4630,2215 4660,2215 4660,2245 350,2315 390,2315 1055,2490 1085,2490 1415,2490 1445,2490 1210,2500 1290,2500 1055,2520 1085,2520 1415,2520 1445,2520 3185,2545 3015,2590 350,2775 390,2775 3475,2805 3475,2865 1575,3090 1605,3090 1575,3160 1605,3160 1050,3230 1632,3240 3455,3245 3485,3245 3515,3245 2050,3260 1050,3265 1575,3270 1605,3270 2000,3270 1050,3520 1050,3555 1630,3585 1610,3675 1580,3725 1580,3755
  other v3: 2503.15,2746.4 2577.95,2746.4 2652.76,2746.4 2727.56,2746.4 2802.36,2746.4 3961.81,2746.4 4036.61,2746.4 4111.42,2746.4 4186.22,2746.4 4261.02,2746.4 2503.15,2761.16 2577.95,2761.16 2652.76,2761.16 2727.56,2761.16 2802.36,2761.16 3961.81,2761.16 4036.61,2761.16 4111.42,2761.16 4186.22,2761.16 4261.02,2761.16 2503.15,2775.93 2577.95,2775.93 2652.76,2775.93 2727.56,2775.93 2802.36,2775.93 3961.81,2775.93 4036.61,2775.93 4111.42,2775.93 4186.22,2775.93 4261.02,2775.93 2503.15,2790.69 2577.95,2790.69 2652.76,2790.69 2727.56,2790.69 2802.36,2790.69 3961.81,2790.69 4036.61,2790.69 4111.42,2790.69 4186.22,2790.69 4261.02,2790.69 2503.15,2805.45 2577.95,2805.45 2652.76,2805.45 2727.56,2805.45 2802.36,2805.45 3961.81,2805.45 4036.61,2805.45 4111.42,2805.45 4186.22,2805.45 4261.02,2805.45 2503.15,2820.22 2577.95,2820.22 2652.76,2820.22 2727.56,2820.22 2802.36,2820.22 3961.81,2820.22 4036.61,2820.22 4111.42,2820.22 4186.22,2820.22 4261.02,2820.22 2503.15,2834.98 2577.95,2834.98 2652.76,2834.98 2727.56,2834.98 2802.36,2834.98 3961.81,2834.98 4036.61,2834.98 4111.42,2834.98 4186.22,2834.98 4261.02,2834.98 2503.15,2849.74 2577.95,2849.74 2652.76,2849.74 2727.56,2849.74 2802.36,2849.74 3961.81,2849.74 4036.61,2849.74 4111.42,2849.74 4186.22,2849.74 4261.02,2849.74 2503.15,2864.51 2577.95,2864.51 2652.76,2864.51 2727.56,2864.51 2802.36,2864.51 3961.81,2864.51 4036.61,2864.51 4111.42,2864.51 4186.22,2864.51 4261.02,2864.51 2503.15,2879.27 2577.95,2879.27 2652.76,2879.27 2727.56,2879.27 2802.36,2879.27 3961.81,2879.27 4036.61,2879.27 4111.42,2879.27 4186.22,2879.27 4261.02,2879.27 2503.15,2894.04 2577.95,2894.04 2652.76,2894.04 2727.56,2894.04 2802.36,2894.04 3961.81,2894.04 4036.61,2894.04 4111.42,2894.04 4186.22,2894.04 4261.02,2894.04 2503.15,2908.8 2577.95,2908.8 2652.76,2908.8 2727.56,2908.8 2802.36,2908.8 3961.81,2908.8 4036.61,2908.8 4111.42,2908.8 4186.22,2908.8 4261.02,2908.8 2503.15,2923.56 2577.95,2923.56 2652.76,2923.56 2727.56,2923.56 2802.36,2923.56 3961.81,2923.56 4036.61,2923.56 4111.42,2923.56 4186.22,2923.56 4261.02,2923.56 2503.15,2938.33 2577.95,2938.33 2652.76,2938.33 2727.56,2938.33 2802.36,2938.33 3961.81,2938.33 4036.61,2938.33 4111.42,2938.33 4186.22,2938.33 4261.02,2938.33 2503.15,2953.09 2577.95,2953.09 2652.76,2953.09 2727.56,2953.09 2802.36,2953.09 3961.81,2953.09 4036.61,2953.09 4111.42,2953.09 4186.22,2953.09 4261.02,2953.09 2503.15,2967.85 2577.95,2967.85 2652.76,2967.85 2727.56,2967.85 2802.36,2967.85 3961.81,2967.85 4036.61,2967.85 4111.42,2967.85 4186.22,2967.85 4261.02,2967.85 2503.15,2982.62 2577.95,2982.62 2652.76,2982.62 2727.56,2982.62 2802.36,2982.62 3961.81,2982.62 4036.61,2982.62 4111.42,2982.62 4186.22,2982.62 4261.02,2982.62 2503.15,2997.38 2577.95,2997.38 2652.76,2997.38 2727.56,2997.38 2802.36,2997.38 3961.81,2997.38 4036.61,2997.38 4111.42,2997.38 4186.22,2997.38 4261.02,2997.38 2503.15,3012.15 2577.95,3012.15 2652.76,3012.15 2727.56,3012.15 2802.36,3012.15 3961.81,3012.15 4036.61,3012.15 4111.42,3012.15 4186.22,3012.15 4261.02,3012.15 2503.15,3026.91 2577.95,3026.91 2652.76,3026.91 2727.56,3026.91 2802.36,3026.91 3961.81,3026.91 4036.61,3026.91 4111.42,3026.91 4186.22,3026.91 4261.02,3026.91 2503.15,3041.67 2577.95,3041.67 2652.76,3041.67 2727.56,3041.67 2802.36,3041.67 3961.81,3041.67 4036.61,3041.67 4111.42,3041.67 4186.22,3041.67 4261.02,3041.67 2503.15,3056.44 2577.95,3056.44 2652.76,3056.44 2727.56,3056.44 2802.36,3056.44 3961.81,3056.44 4036.61,3056.44 4111.42,3056.44 4186.22,3056.44 4261.02,3056.44 2503.15,3071.2 2577.95,3071.2 2652.76,3071.2 2727.56,3071.2 2802.36,3071.2 3961.81,3071.2 4036.61,3071.2 4111.42,3071.2 4186.22,3071.2 4261.02,3071.2 2503.15,3085.97 2577.95,3085.97 2652.76,3085.97 2727.56,3085.97 2802.36,3085.97 3961.81,3085.97 4036.61,3085.97 4111.42,3085.97 4186.22,3085.97 4261.02,3085.97 2503.15,3100.73 2577.95,3100.73 2652.76,3100.73 2727.56,3100.73 2802.36,3100.73 3961.81,3100.73 4036.61,3100.73 4111.42,3100.73 4186.22,3100.73 4261.02,3100.73 2503.15,3115.49 2577.95,3115.49 2652.76,3115.49 2727.56,3115.49 2802.36,3115.49 3961.81,3115.49 4036.61,3115.49 4111.42,3115.49 4186.22,3115.49 4261.02,3115.49 2503.15,3130.26 2577.95,3130.26 2652.76,3130.26 2727.56,3130.26 2802.36,3130.26 3961.81,3130.26 4036.61,3130.26 4111.42,3130.26 4186.22,3130.26 4261.02,3130.26 2503.15,3145.02 2577.95,3145.02 2652.76,3145.02 2727.56,3145.02 2802.36,3145.02 3961.81,3145.02 4036.61,3145.02 4111.42,3145.02 4186.22,3145.02 4261.02,3145.02 2503.15,3159.78 2577.95,3159.78 2652.76,3159.78 2727.56,3159.78 2802.36,3159.78 3961.81,3159.78 4036.61,3159.78 4111.42,3159.78 4186.22,3159.78 4261.02,3159.78 2503.15,3174.55 2577.95,3174.55 2652.76,3174.55 2727.56,3174.55 2802.36,3174.55 3961.81,3174.55 4036.61,3174.55 4111.42,3174.55 4186.22,3174.55 4261.02,3174.55 2503.15,3189.31 2577.95,3189.31 2652.76,3189.31 2727.56,3189.31 2802.36,3189.31 3961.81,3189.31 4036.61,3189.31 4111.42,3189.31 4186.22,3189.31 4261.02,3189.31 2503.15,3204.08 2577.95,3204.08 2652.76,3204.08 2727.56,3204.08 2802.36,3204.08 3961.81,3204.08 4036.61,3204.08 4111.42,3204.08 4186.22,3204.08 4261.02,3204.08 2503.15,3218.84 2577.95,3218.84 2652.76,3218.84 2727.56,3218.84 2802.36,3218.84 3961.81,3218.84 4036.61,3218.84 4111.42,3218.84 4186.22,3218.84 4261.02,3218.84 2503.15,3233.6 2577.95,3233.6 2652.76,3233.6 2727.56,3233.6 2802.36,3233.6 3961.81,3233.6 4036.61,3233.6 4111.42,3233.6 4186.22,3233.6 4261.02,3233.6 2503.15,3248.37 2577.95,3248.37 2652.76,3248.37 2727.56,3248.37 2802.36,3248.37 3961.81,3248.37 4036.61,3248.37 4111.42,3248.37 4186.22,3248.37 4261.02,3248.37 2503.15,3263.13 2577.95,3263.13 2652.76,3263.13 2727.56,3263.13 2802.36,3263.13 3961.81,3263.13 4036.61,3263.13 4111.42,3263.13 4186.22,3263.13 4261.02,3263.13 2503.15,3277.89 2577.95,3277.89 2652.76,3277.89 2727.56,3277.89 2802.36,3277.89 3961.81,3277.89 4036.61,3277.89 4111.42,3277.89 4186.22,3277.89 4261.02,3277.89 2503.15,3292.66 2577.95,3292.66 2652.76,3292.66 2727.56,3292.66 2802.36,3292.66 3961.81,3292.66 4036.61,3292.66 4111.42,3292.66 4186.22,3292.66 4261.02,3292.66 2503.15,3307.42 2577.95,3307.42 2652.76,3307.42 2727.56,3307.42 2802.36,3307.42 3961.81,3307.42 4036.61,3307.42 4111.42,3307.42 4186.22,3307.42 4261.02,3307.42 2503.15,3322.19 2577.95,3322.19 2652.76,3322.19 2727.56,3322.19 2802.36,3322.19 3961.81,3322.19 4036.61,3322.19 4111.42,3322.19 4186.22,3322.19 4261.02,3322.19 2503.15,3336.95 2577.95,3336.95 2652.76,3336.95 2727.56,3336.95 2802.36,3336.95 3961.81,3336.95 4036.61,3336.95 4111.42,3336.95 4186.22,3336.95 4261.02,3336.95 2503.15,3351.71 2577.95,3351.71 2652.76,3351.71 2727.56,3351.71 2802.36,3351.71 3961.81,3351.71 4036.61,3351.71 4111.42,3351.71 4186.22,3351.71 4261.02,3351.71 2503.15,3366.48 2577.95,3366.48 2652.76,3366.48 2727.56,3366.48 2802.36,3366.48 3961.81,3366.48 4036.61,3366.48 4111.42,3366.48 4186.22,3366.48 4261.02,3366.48 2503.15,3381.24 2577.95,3381.24 2652.76,3381.24 2727.56,3381.24 2802.36,3381.24 3961.81,3381.24 4036.61,3381.24 4111.42,3381.24 4186.22,3381.24 4261.02,3381.24 2503.15,3396.01 2577.95,3396.01 2652.76,3396.01 2727.56,3396.01 2802.36,3396.01 3961.81,3396.01 4036.61,3396.01 4111.42,3396.01 4186.22,3396.01 4261.02,3396.01 2503.15,3410.77 2577.95,3410.77 2652.76,3410.77 2727.56,3410.77 2802.36,3410.77 3961.81,3410.77 4036.61,3410.77 4111.42,3410.77 4186.22,3410.77 4261.02,3410.77 2503.15,3425.53 2577.95,3425.53 2652.76,3425.53 2727.56,3425.53 2802.36,3425.53 3961.81,3425.53 4036.61,3425.53 4111.42,3425.53 4186.22,3425.53 4261.02,3425.53 2503.15,3440.3 2577.95,3440.3 2652.76,3440.3 2727.56,3440.3 2802.36,3440.3 3961.81,3440.3 4036.61,3440.3 4111.42,3440.3 4186.22,3440.3 4261.02,3440.3 2503.15,3455.06 2577.95,3455.06 2652.76,3455.06 2727.56,3455.06 2802.36,3455.06 3961.81,3455.06 4036.61,3455.06 4111.42,3455.06 4186.22,3455.06 4261.02,3455.06 2503.15,3469.82 2577.95,3469.82 2652.76,3469.82 2727.56,3469.82 2802.36,3469.82 3961.81,3469.82 4036.61,3469.82 4111.42,3469.82 4186.22,3469.82 4261.02,3469.82 2503.15,3484.59 2577.95,3484.59 2652.76,3484.59 2727.56,3484.59 2802.36,3484.59 3961.81,3484.59 4036.61,3484.59 4111.42,3484.59 4186.22,3484.59 4261.02,3484.59
  other v4: 4505.71,2153.94
  other v5: 3411.42,2269.8 3360.24,2320.98 3539.37,2320.98 3411.42,2551.3 3539.37,2551.3 3479,2699 3539.43,2704.43 3603.86,2704.43 3301,2849 3215,2895 3525,2915 3205,2945 3205,2975 3329,3027
  other v6: 2629.53,1936.42 4492.91,1936.42 2611.07,1946.01 2647.98,1946.01 4474.46,1946.01 4511.37,1946.01 2603.94,1962.01 4467.32,1962.01 2611.07,1978.01 2647.98,1978.01 4474.46,1978.01 4511.37,1978.01 2629.53,1987.6 4492.91,1987.6 2611.07,1997.19 2647.98,1997.19 4474.46,1997.19 4511.37,1997.19 2603.94,2013.19 4467.32,2013.19 2611.07,2029.19 2647.98,2029.19 4474.46,2029.19 4511.37,2029.19 2629.53,2038.78 4492.91,2038.78 2611.07,2048.37 2647.98,2048.37 4474.46,2048.37 4511.37,2048.37 2603.94,2064.37 4467.32,2064.37 2611.07,2080.37 2647.98,2080.37 4474.46,2080.37 4511.37,2080.37 2373.62,2089.96 2424.8,2089.96 2475.98,2089.96 2527.17,2089.96 2629.53,2089.96 4237.01,2089.96 4288.19,2089.96 4339.37,2089.96 4390.55,2089.96 4492.91,2089.96 2357.62,2097.09 2389.62,2097.09 2408.8,2097.09 2440.8,2097.09 2459.98,2097.09 2491.98,2097.09 2511.17,2097.09 2543.17,2097.09 4221.01,2097.09 4253.01,2097.09 4272.19,2097.09 4304.19,2097.09 4323.37,2097.09 4355.37,2097.09 4374.55,2097.09 4406.55,2097.09 2348.03,2115.55 2399.21,2115.55 2450.39,2115.55 2501.57,2115.55 2552.76,2115.55 4211.42,2115.55 4262.6,2115.55 4313.78,2115.55 4364.96,2115.55 4416.14,2115.55 2357.62,2134.01 2389.62,2134.01 2408.8,2134.01 2440.8,2134.01 2459.98,2134.01 2491.98,2134.01 2511.17,2134.01 2543.17,2134.01 4221.01,2134.01 4253.01,2134.01 4272.19,2134.01 4304.19,2134.01 4323.37,2134.01 4355.37,2134.01 4374.55,2134.01 4406.55,2134.01
  other v7: 2980,2430
  other v9: 1955,676.54 1955,710 1955,743.46 1072.16,1812.17 1117.83,1812.17 1095,1835 1072.16,1857.83 1117.83,1857.83 695,2277.6 672.36,2315 717.64,2315 695,2352.4 1250,2528.35 1250,2571.65 1682.01,3399.39 1720.39,3399.39 1769.61,3399.39 1682.01,3448.61 1720.39,3448.61 1769.61,3448.61 1807.99,3448.61 1720.39,3486.99 1769.61,3486.99
MDIO_CLK: R112.1 U14.R19 | length 3121.6
  Layer 3 - Signal (Sensitive) w5: v2(3105,3515) 3125,3495 3775,3495 3885,3385 3885,2765 3790,2670 v7(3790,2600)
  Layer 8 - Bottom Layer w5.5: U14.R19@3705.71,2564.09 3707.61,2566 3739,2566 3773,2600 v7(3790,2600)
  Layer 8 - Bottom Layer w8: R112.1@1885,3252.01 1885,3251.22 1889.27,3246.95 1890.06,3246.95 1927.01,3210 2700,3210 3005,3515 v2(3105,3515)
MDIO_DATA: R15.1 R16.1 U14.P19 | length 3170.3
  Layer 1 - Top Layer w8: R16.1@2037.99,3320 R15.1@2091.38,3320 2091.38,3356.38 2165,3430 v2(2165,3485)
  Layer 3 - Signal (Sensitive) w5: v2(2165,3485) 2175,3495 2980,3495 3060,3575 3130,3575 3160,3545 3345,3545 3380,3580 3750,3580 3935,3395 3935,2715 3845,2625 3845,2589.57 v7(3825.22,2569.78)
  Layer 8 - Bottom Layer w5.5: U14.P19@3705.71,2538.5 3714.5,2538.5 3718,2542 3739,2542 3748,2533 3788.43,2533 v7(3825.22,2569.78)
NetC5_2: C5.2 R18.2 R23.1 | length 150
  Layer 1 - Top Layer w20: R23.1@478.62,2700 R18.2@478.62,2850
NetC35_2: C35.2 R33.2 R38.1 | length 150
  Layer 1 - Top Layer w20: R38.1@478.62,2240 R33.2@478.62,2390
NetC40_1: C40.1 C43.1 C45.1 R44.1 U5.A2 U5.B2
NetC41_1: C41.1 C44.1 C46.1 R45.1 U6.A2 U6.B2
NetC49_2: C49.2 R51.1 R57.2 U7.4 | length 185.6
  Layer 1 - Top Layer w15: R57.2@838.62,1910 835,1913.62 835,1983.46 U7.4@839.13,1987.6 847.01,1987.6 864.72,2005.31 C49.2@890,2005.31 891.97,2003.35 933.03,2003.35 R51.1@935,2001.38
NetC58_1: C58.1 U6.A13 | length 150.4
  Layer 1 - Top Layer w10: U6.A13@4518.5,1834.06 4534.33,1834.06 4553.39,1815 4553.39,1755 4543.39,1745 C58.1@4543.39,1711.5
NetC59_1: C59.1 U5.A13 | length 157.1
  Layer 1 - Top Layer w10: U5.A13@2655.12,1834.06 2670.94,1834.06 2690,1815 2690,1738 2678,1726 2678,1708.5 C59.1@2680,1706.5
NetC60_1: C60.1 L2.1 L3.4 R238.2
NetC61_1: C61.1 U6.E14 | length 140.5
  Layer 1 - Top Layer w5: C61.1@4368.62,1690 4372.56,1690 4401.89,1719.33 4401.89,1794.21 U6.E14@4416.14,1808.46
NetC62_1: C62.1 U5.F14 Y1.3 | length 265.9
  Layer 1 - Top Layer w5: C62.1@2353.61,1669.81 2360.79,1677 2396.61,1677 2412.78,1693.17 Y1.3@2412.78,1696.44 2412.78,1705.39 2451.72,1744.33 2509.72,1744.33 2528.17,1762.78 U5.F14@2528.17,1808.46
NetC63_1: C63.1 C71.1 L2.2 L4.1 R60.2
NetC66_1: C66.1 U5.E14 Y1.1 | length 355.5
  Layer 1 - Top Layer w5: C66.1@2470.34,1550.6 2475,1555.26 2475,1601.18 Y1.1@2485.61,1611.79 2485.61,1619.67 2450,1655.28 2450,1728 2456,1734 2514,1734 2538.5,1758.5 2538.5,1794.21 U5.E14@2552.76,1808.46
NetC72_1: C72.1 R60.1
NetC75_1: C75.1 D8.1 L3.1 R61.2 R238.1
NetC75_2: C75.2 C81.2 C85.2 C88.2 D9.1 J10.2 J10.S1 J10.S2 L3.2 R239.1
NetC81_1: C81.1 R61.1
NetC83_2: C83.2 R68.2 | length 53.3
  Layer 1 - Top Layer w10: C83.2@713.5,775 720,781.5 720,823.62 R68.2@721.38,825
NetC85_1: C85.1 C88.1 D8.2 D9.2 J10.1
